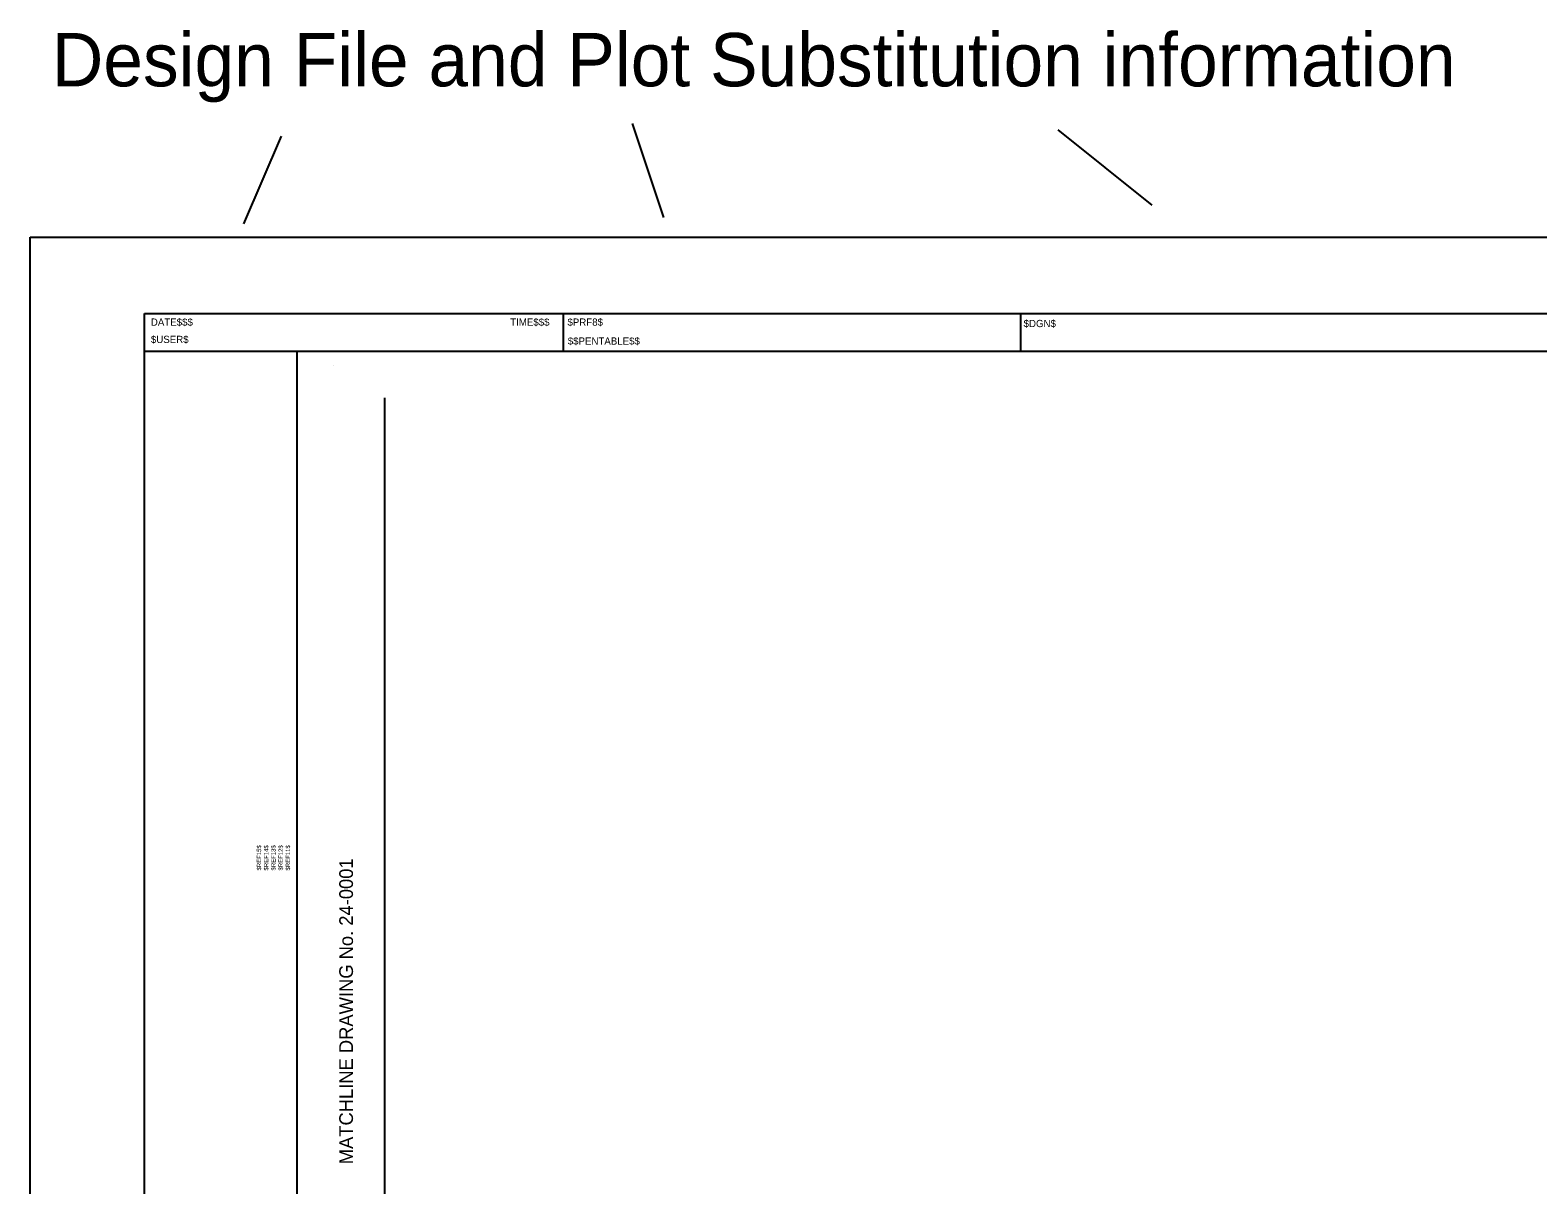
# Model space of a CAD drawing. Extents: x 2158280 to 2158980, y 1040586 to 1041166.
# Drawn here: x 2158279.6 to 2158675.2, y 1040863.5 to 1041166.5 of the extents above; entities that cross this region are included whole.
import ezdxf

# ---------------------------------------------------------------- set-up
doc = ezdxf.new("R2010")
doc.units = 0
for name, color, linetype in [('SHT_B_MainLine-Text', 7, 'Continuous'), ('SHT_B_Major-Elevation-Tic-Line', 7, 'Continuous'), ('SHT_B_Minor-Station-Tic-Line', 7, 'Continuous'), ('SHT_B_North-Arrow', 7, 'Continuous'), ('UTLE_E_UG-Wat-Line-30-Qual-B-50', 7, 'Continuous'), ('UTLE_E_UG-Wat-Line-30-Qual-C-50', 7, 'Continuous')]:
    doc.layers.add(name, color=color, linetype=linetype)

msp = doc.modelspace()

# ---------------------------------------------------------------- linework, layer by layer
at = {"layer": 'SHT_B_MainLine-Text'}
msp.add_line((2158372.56, 1041070), (2158372.56, 1040725.2), dxfattribs=at)
at = {"layer": 'SHT_B_North-Arrow'}
for p, q in [((2158437.5, 1041141.97), (2158445.72, 1041117.31)), ((2158549.28, 1041140.33), (2158573.92, 1041120.59)), ((2158345.44, 1041138.69), (2158335.58, 1041115.67)), ((2158419.56, 1041082.15), (2158419.56, 1041092.15)), ((2158539.56, 1041082.15), (2158539.56, 1041092.15)), ((2158969.56, 1041082.15), (2158309.56, 1041082.15)), ((2158349.56, 1041082.15), (2158349.56, 1040672.15)), ((2158359.56, 1041082.15), (2158359.56, 1041082.15)), ((2158359.56, 1041082.15), (2158359.56, 1041082.15)), ((2158359.06, 1041078.35), (2158359.06, 1041078.35))]:
    msp.add_line(p, q, dxfattribs=at)
at = {"layer": 'UTLE_E_UG-Wat-Line-30-Qual-B-50'}
msp.add_lwpolyline([(2158309.56, 1041092.15), (2158969.56, 1041092.15), (2158969.56, 1040672.15), (2158309.56, 1040672.15)], close=True, dxfattribs=at)
at = {"layer": 'UTLE_E_UG-Wat-Line-30-Qual-C-50'}
msp.add_lwpolyline([(2158279.56, 1041112.15), (2158979.56, 1041112.15), (2158979.56, 1040652.15), (2158279.56, 1040652.15)], close=True, dxfattribs=at)

# ---------------------------------------------------------------- texts
at = {"layer": 'SHT_B_Major-Elevation-Tic-Line'}
msp.add_text('MATCHLINE DRAWING No. 24-0001', height=3.6, rotation=90, dxfattribs=at).set_placement((2158364.28, 1040868.89))
at = {"layer": 'SHT_B_Minor-Station-Tic-Line'}
for s, height, rotation, p in [('DATE$$$', 1.9, 0, (2158311.24, 1041088.91)), ('TIME$$$', 1.9, 0, (2158405.54, 1041088.91)), ('$PRF8$', 1.9, 0, (2158420.56, 1041088.91)), ('$DGN$', 1.9, 0, (2158540.26, 1041088.55)), ('$USER$', 1.9, 0, (2158311.26, 1041084.37)), ('$$PENTABLE$$', 1.9001, 0, (2158420.64, 1041083.95)), ('$REF15$', 1.134, 90.0013, (2158340.18, 1040945.97)), ('$REF14$', 1.134, 90.0013, (2158342.06, 1040945.97)), ('$REF13$', 1.134, 90.0013, (2158343.96, 1040945.97)), ('$REF12$', 1.134, 90.0013, (2158345.86, 1040945.97)), ('$REF11$', 1.134, 90.0013, (2158347.76, 1040945.97))]:
    msp.add_text(s, height=height, rotation=rotation, dxfattribs=at).set_placement(p)
at = {"layer": 'SHT_B_North-Arrow'}
msp.add_text('Design File and Plot Substitution information', height=14, rotation=0, dxfattribs=at).set_placement((2158285.24, 1041151.73))

doc.saveas('drawing.dxf')
